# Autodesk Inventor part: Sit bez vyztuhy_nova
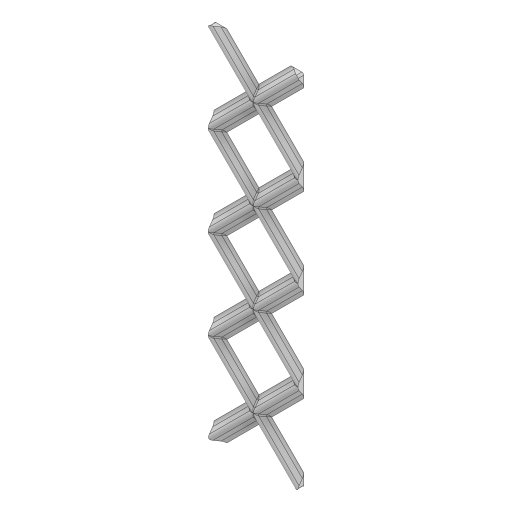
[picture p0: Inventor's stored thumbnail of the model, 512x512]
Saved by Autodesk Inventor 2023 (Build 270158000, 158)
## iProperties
Created: 2025-03
Part Number: Sit bez vyztuhy_nova
Material: Všeobecné
Document SubType Name: Modeling
Designer: tomik
Density: 1 g/cm^3
Appearance: Výchozí
Author: tomik
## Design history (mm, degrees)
sketch "Náčrt1"
  geometry: L1 (0, 0)-(211.67, 0); L2 (0, 0)-(200, 200)
  constraints: 4 end point, 1 horizontal
  dimensions: "d1" = 45 deg angle of L1 L2; "d2" = 200 distance from line of L2.end L1
node "Pracovní rovina2"
sketch "Náčrt2"
  geometry: L1 (0, 0)-(0, 13.004); L2 (0, 0)-(-15.85, 0); L3 (0, 0)-(-4, 0); L4 (-3.268, 0.732)-(0, 4); L5 (0, 0)-(15.85, 0); L6 (0, 0)-(4, 0); L7 (3.268, 0.732)-(0, 4); L8 (0, 0)-(15.85, 0); L9 (5.036, 0)-(-5.036, 0); A1 r 2.5 centre (-5.036, 2.5) between (-5.036, 0) and (-3.268, 0.732); A2 r 2.5 centre (5.036, 2.5) between (3.268, 0.732) and (5.036, 0); 2 further points
  constraints: 18 end point, 5 point on line, 5 symmetric about line, 4 point on circle, 4 tangent, 2 centre point, 1 collinear, 1 horizontal, 1 vertical, 1 other
  dimensions: "d3" = 4 distance of L1.start L3.end; "d4" = 4 distance of L4.end L1.start; "d5" = 5 diameter of A1; "d6" = 5.03553 distance from line of L9.end L1
extrude "Vysunutí1" new body sketch "Náčrt2" distance "d7" = 200; taper "d8" = 0 deg
node "Pracovní rovina6"
fillet "Zaoblení3" dims "d14" = 2
mirror "Zrcadlit3"
node "Pracovní rovina10"
  node "Pracovní rovina9"
node "Pracovní rovina11"
pattern_linear "Obdélníkové pole1"
sketch "Náčrt3"
  geometry: 1 further point
sketch "Náčrt4"
  geometry: L1 (-30.32, -10.071)-(-30.32, 0) reference; L2 (-30.32, 0)-(0, 0) reference; L3 (10.071, -40.391)-(10.071, -10.071) reference; L4 (0, -40.391)-(10.071, -40.391) reference; L5 (-30.32, -3.621)-(-30.32, -6.45) reference; L6 (-30.32, -5.036)-(5.036, -40.391); L7 (-30.32, -5.036)-(111.102, 136.386); L8 (111.102, 136.386)-(146.457, 101.03); L9 (146.457, 101.03)-(5.036, -40.391); L10 (40.391, 415.738)-(-248.096, 101.03); L11 (-248.096, 101.03)-(128.779, -294.975); L12 (128.779, -294.975)-(406.838, 40.162); L13 (406.838, 40.162)-(40.391, 415.738); 7 further points
  constraints: 16 end point, 2 perpendicular, 1 coincident, 1 midpoint
  dimensions: "d23" = 200 distance of L6.start L7.end; "d24" = 50 distance of L7.end L8.end
extrude "Vysunutí2" cut sketch "Náčrt4" distance "d25" = 200; taper "d26" = 0 deg
fillet "Zaoblení5" dims "d27" = 1
fillet "Zaoblení6" dims "d28" = 1
node "Těleso1"
other parameters: "d11" = 25, "d18" = 25
